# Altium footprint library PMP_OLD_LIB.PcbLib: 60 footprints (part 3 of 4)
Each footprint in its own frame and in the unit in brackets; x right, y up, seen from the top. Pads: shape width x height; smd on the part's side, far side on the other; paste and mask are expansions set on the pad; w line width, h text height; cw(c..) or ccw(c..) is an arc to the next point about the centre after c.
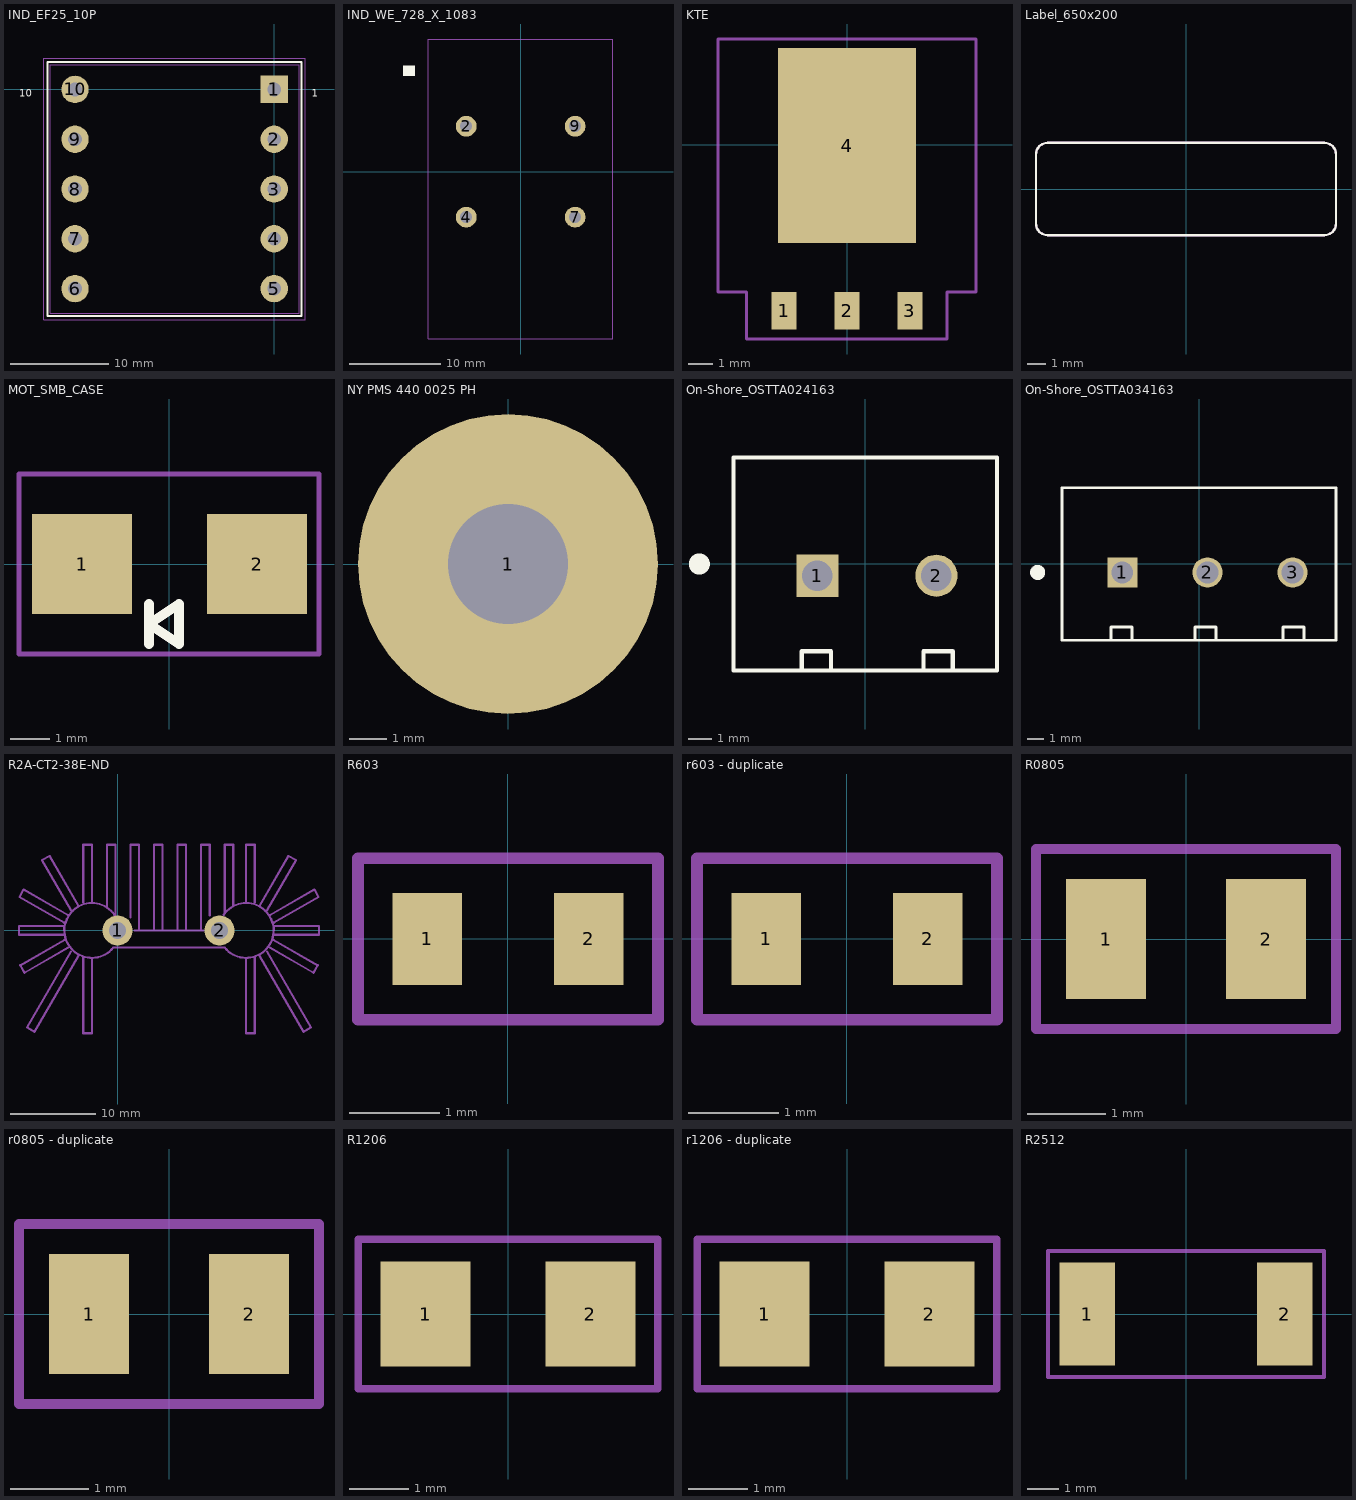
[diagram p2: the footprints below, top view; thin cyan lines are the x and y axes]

## IND_EF25_10P [mil]
pads (10):
  rect 110x110 hole 55: 1(0,0)
  round 110 hole 55: 2(0,-200) 3(0,-400) 4(0,-600) 5(0,-800) 6(-800,-800) 7(-800,-600) 8(-800,-400) 9(-800,-200) 10(-800,0)
Top Overlay:
  lines w8: -910,-910 110,-910 110,110 -910,110 -910,30 -910,-910
  text "10" at -1025,-30 h30
  text "1" at 150,-30 h30
Mechanical 5:
  lines w5: -925,-925 -925,125 125,125 125,-925 -925,-925 ; -900,-900 100,-900 100,100 -900,100 -900,-900
  text "*" at 150,-10 h40
  text ".Designator" at -515,160 h60

## IND_WE_728_X_1083 [mil]
pads (4):
  round 90 hole 52: 2(-236,197) 4(-236,-197) 7(236,-197) 9(236,197)
Top Overlay:
  region: -510,415 -460,415 -460,460 -510,460
Mechanical 5:
  lines w5: -400,-725 -400,575 400,575 400,-725 -400,-725
  text ".Designator" at 425,-45 h60
  text "*" at -350,475 h30

## KTE [mil]
pads (4):
  rect 40x60 smd: 1(-100,-264) 2(0,-264) 3(100,-264)
  rect 220x310 smd: 4(0,-1.7)
Mechanical 5:
  lines w5: -205,-234 -160,-234 -160,-309 159,-309 159,-234 205,-234 205,168 -205,168 -205,-234
  text ".Designator" at -120,295 h60

## Label_650x200 [mil] "Thermal Transfer Label"
height 1
pads (1):
  round 1 on Mech13: 0(0,0)
Top Overlay:
  lines w5: -325,-75 ccw(c-300,-75) -300,-100 300,-100 ccw(c300,-75) 325,-75 325,75 ccw(c300,75) 300,100 -300,100 ccw(c-300,75) -325,75 -325,-75
Mechanical 5:
  lines w5: -325,-75 ccw(c-300,-75) -300,-100 300,-100 ccw(c300,-75) 325,-75 325,75 ccw(c300,75) 300,100 -300,100 ccw(c-300,75) -325,75 -325,-75
  text ".Designator" at -60,-20 h40
3D body: height 1, standoff 0, extent -325.51,-100.51 325.51,100.51

## MOT_SMB_CASE [mil]
pads (2):
  rect 100x100 smd: 1(-87,0) 2(88,0)
Top Overlay:
  lines w10.1: -20,-80 -20,-40 ; -20,-60 10,-40 10,-80 -20,-60
Mechanical 5:
  lines w5: -20,-80 -20,-40 ; -150,-90 150,-90 150,90 -150,90 -150,-90 ; -20,-60 10,-40 10,-80 -20,-60
  text ".Designator" at -112,-186 h60

## NY PMS 440 0025 PH [mm] "4-40 nylon screw and mounting hole"
height 1.905
pads (1):
  round 8 hole 3.2: 1(0,0)
Mechanical 5:
  circle w0.127: c0,0 r3.789
3D body: height 2.69, standoff -8.74, extent -3.302,-3.3 3.296,3.3

## On-Shore_OSTTA024163 [mm] "TERM BLOCK 2x1, 5.08mm, TH"
height 13
pads (2):
  rect 1.8x1.8 hole 1.3: 1(-2.04,-0.5)
  round 1.8 hole 1.3 paste+0: 2(3.04,-0.5)
Top Overlay:
  circle w0.7: c-7.085,0 r0.1
  lines w0.178: -2.713,-4.55 -2.713,-3.726 -1.463,-3.726 -1.463,-4.55 ; 2.487,-4.55 2.487,-3.726 3.737,-3.726 3.737,-4.55 ; -5.63,-4.55 5.63,-4.55 5.63,4.55 -5.63,4.55 -5.63,-4.55
Mechanical 5:
  lines w0.1: -2.713,-4.551 -2.713,-3.726 -1.463,-3.726 -1.463,-4.55 ; 2.487,-4.551 2.487,-3.726 3.737,-3.726 3.737,-4.55 ; -5.63,-4.55 -5.63,4.55 5.63,4.55 5.63,-4.55 -5.63,-4.55
  text ".Designator" at -8.534,-0.584 h1.52
3D body: height 13, standoff 0, extent -5.68,-4.601 5.68,4.6

## On-Shore_OSTTA034163 [mm] "TERM BLOCK 3x1, 5.08mm, TH"
height 13
pads (3):
  rect 1.8x1.8 hole 1.3: 1(-4.58,-0.5)
  round 1.8 hole 1.3 paste+0: 2(0.5,-0.5) 3(5.58,-0.5)
Top Overlay:
  circle w0.7: c-9.633,-0.5 r0.1
  lines w0.178: -5.25,-4.55 -5.25,-3.75 -4,-3.75 -4,-4.55 ; -0.25,-4.55 -0.25,-3.75 1,-3.75 1,-4.55 ; 5,-4.55 5,-3.75 6.25,-3.75 6.25,-4.55 ; -8.17,-4.55 8.17,-4.55 8.17,4.55 -8.17,4.55 -8.17,-4.55
Mechanical 5:
  lines w0.1: -5.25,-4.55 -5.25,-3.75 -4,-3.75 -4,-4.55 ; -0.25,-4.55 -0.25,-3.75 1,-3.75 1,-4.55 ; 5,-4.55 5,-3.75 6.25,-3.75 6.25,-4.55 ; -8.17,-4.55 8.17,-4.55 8.17,4.55 -8.17,4.55 -8.17,-4.55
  text ".Designator" at -8.636,-1.524 h1.52
3D body: height 13, standoff 0, extent -8.22,-4.6 8.22,4.6

## R2A-CT2-38E-ND [mm] "HEATSINK FOR TO-220"
height 39
pads (2):
  round 3.5 hole 2: 1(0,0) 2(11.9,0)
Mechanical 5:
  lines w0.254: -6.255,0.905 -11.45,3.904 -10.95,4.77 -5.755,1.771 ; -6.25,-0.5 -11.5,-0.5 -11.5,0.5 -6.25,0.5 -6.25,0 ; -6.196,-1.093 -11.353,-4.071 -10.853,-4.937 -5.754,-1.993 ; -5.433,2.353 -8.808,8.199 -7.942,8.699 -4.567,2.853 ; -5.43,-2.464 -10.548,-11.328 -9.682,-11.828 -4.564,-2.964 ; -4,-3.25 -4,-12 -3,-12 ; -4,3.25 -4,10 -3,10 -3,3.25 ; -3,-3.25 -3,-12 ; -1.25,2.75 -1.25,10 -0.25,10 -0.25,1.836 ; -0.377,1.836 ccw(c-3,0) -0.5,-2 12.5,-2 ccw(c15,0) 12.377,1.836 ; 1.5,1.5 1.5,10 2.5,10 2.5,0 ; 2,0 10,0 ; 4.25,0 4.25,10 5.25,10 5.25,0 ; 7,0 7,10 8,10 8,0 ; 9.75,0 9.75,10 10.75,10 10.75,1.75 ; 12.5,2 12.5,10 13.5,10 13.5,3 ; 15,-4.5 15,-12 ; 15,-3.25 15,-12 ; 15,3.25 15,10 ; 15,5 15,10 ; 16,-3.25 16,-12 15,-12 ; 16,3.25 16,10 15,10 ; 16.564,-2.964 21.682,-11.828 22.548,-11.328 17.43,-2.464 ; 16.567,2.853 19.942,8.699 20.808,8.199 17.433,2.353 ; 17.754,-1.993 22.853,-4.937 23.353,-4.071 18.196,-1.093 ; 17.755,1.771 22.95,4.77 23.45,3.904 18.255,0.905 ; 18.25,-0.5 23.5,-0.5 23.5,0.5 18.25,0.5 18.25,0 ; -3,-12 -3,-12 ; -3,-12 -3,-12 ; 15,-12 15,-12 ; 15,-12 15,-12 ; 15,-12 15,-12

## R603 [mil]
pads (2):
  rect 30x40 smd: 1(-35,0) 2(35,0)
Mechanical 5:
  lines w5: -65,-35 65,-35 65,35 -65,35 -65,-35
  text ".Designator" at 260,25 h60

## r603 - duplicate [mil]
pads (2):
  rect 30x40 smd: 1(-35,0) 2(35,0)
Mechanical 5:
  lines w5: -65,-35 65,-35 65,35 -65,35 -65,-35
  text ".Designator" at -96,37 h60

## R0805 [mil]
pads (2):
  rect 40x60 smd: 1(-40,0) 2(40,0)
Mechanical 5:
  lines w5: -75,-45 -75,45 75,45 75,-45 -75,-45
  text ".Designator" at 5,60 h60

## r0805 - duplicate [mil]
pads (2):
  rect 40x60 smd: 1(-40,0) 2(40,0)
Mechanical 5:
  lines w5: -75,-45 -75,45 75,45 75,-45 -75,-45
  text ".Designator" at -45,65 h60

## R1206 [mil]
pads (2):
  rect 60x70 smd: 1(-55,0) 2(55,0)
Mechanical 5:
  lines w5: -100,-50 100,-50 100,50 -100,50 -100,-50
  text ".Designator" at 80,-80 h60

## r1206 - duplicate [mil]
pads (2):
  rect 60x70 smd: 1(-55,0) 2(55,0)
Mechanical 5:
  lines w5: -100,-50 100,-50 100,50 -100,50 -100,-50
  text ".Designator" at 129,-46 h60

## R2512 [mil]
pads (2):
  rect 70x130 smd: 1(-125,0) 2(125,0)
Mechanical 5:
  lines w5: -175,-80 175,-80 175,80 -175,80 -175,-80
  text ".Designator" at 65,-110 h60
